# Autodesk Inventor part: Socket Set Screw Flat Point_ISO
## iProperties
Created: 2011-02
Part Number: Socket Set Screw Flat Point_ISO
Document SubType Name: Modeling
Designer: eric
Density: 1 g/cm^3
Author: eric
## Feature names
1. Base1
